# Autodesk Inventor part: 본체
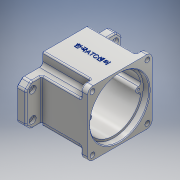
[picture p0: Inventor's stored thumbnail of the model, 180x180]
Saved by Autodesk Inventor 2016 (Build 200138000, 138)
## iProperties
Created: 2017-01
Part Number: 본체
Material: 알루미늄 6061
Document SubType Name: Modeling
Designer: Owner
Mass: 876.665 g
Surface Area: 765.409 cm^2
Volume: 324.691 cm^3
Density: 2.7 g/cm^3
Appearance: 알루미늄 - 평지
Author: Owner
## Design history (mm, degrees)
sketch "스케치1"
  geometry: L1 (-47, 47)-(47, 47); L2 (47, 47)-(47, -47); L3 (47, -47)-(-47, -47); L4 (-47, -47)-(-47, 47); L5 (-47, 47)-(47, -47); L6 (47, 47)-(-47, -47); 1 further point
  constraints: 12 end point, 2 midpoint, 2 parallel, 1 horizontal, 1 perpendicular
  dimensions: "d0" = 94 distance of L2.end L3.end; "d1" = 94 distance of L1.end L2.end
extrude "돌출1" new body sketch "스케치1" distance "d2" = 80; taper "d3" = 0 deg
sketch "스케치2"
  geometry: L1 (30, 70)-(-30, 70); L2 (-30, -70)-(30, -70); L3 (30, 70)-(-30, -70); L4 (-30, 70)-(30, -70); L5 (47, -33)-(47, 33); L6 (-47, 33)-(-47, -33); L7 (-47, -33)-(47, 33); L8 (47, -33)-(-47, 33); L9 (-47, -33)-(-30, -33); L10 (30, -33)-(47, -33); L11 (30, -70)-(30, -33); L12 (30, 33)-(30, 70); L13 (47, 33)-(30, 33); L14 (-30, 33)-(-47, 33); L15 (-30, 70)-(-30, 33); L16 (-30, -33)-(-30, -70); 9 further points
  constraints: 32 end point, 12 midpoint, 10 parallel, 4 perpendicular, 3 horizontal, 2 horizontal alignment, 2 vertical alignment
  dimensions: "d4" = 60 distance of L2.start L2.end; "d5" = 66 distance of L5.start L5.end; "d6" = 140 distance between parallel lines of L2 L1; "d7" = 94 distance between parallel lines of L6 L5
extrude "돌출2" join sketch "스케치2" distance "d8" = 13; taper "d9" = 0 deg
sketch "스케치3"
  geometry: L1 (47, -47)-(47, 47) reference; L2 (47, -47)-(30, -47); L3 (30, -47)-(30, -33); L4 (30, -33)-(47, -33); L5 (47, -33)-(47, -47); 1 further point
  constraints: 8 end point, 2 parallel, 1 horizontal, 1 perpendicular
  dimensions: "d10" = 17 distance of L3.end L4.end; "d11" = 14 distance of L2.end L3.end
extrude "돌출3" cut sketch "스케치3" distance "d12" = 70; taper "d13" = 0 deg
hole "구멍1" diameter "d32" = 80; stored, may be unused: countersink angle "d36" = 90 deg, drill point angle "d38" = 0 deg; dims "d30" = 47, "d31" = 47, "d33" = 6, "d34" = 4, "d35" = 2, "d37" = 71
hole "구멍2" diameter "d41" = 86; stored, may be unused: countersink angle "d45" = 90 deg, drill point angle "d47" = 0 deg; dims "d39" = 10, "d40" = 10, "d42" = 6, "d43" = 4, "d44" = 2, "d46" = 9
sketch "스케치8"
  geometry: A1 r 21 centre (-11, 0) between (7.984, 8.978) and (7.984, -8.978); A2 r 15 centre (20, 0) between (7.984, -8.978) and (7.984, 8.978); 1 further point
  constraints: 4 point on circle, 2 centre point, 2 horizontal alignment
  dimensions: "d48" = 42 diameter of A1; "d49" = 11 distance of point (0, 0) A1.centre; "d50" = 30 diameter of A2; "d51" = 20 distance of point (0, 0) A2.centre
extrude "돌출6" join sketch "스케치8" distance "d52" = 7; taper "d53" = 0 deg
hole "구멍3" diameter "d56" = 22; stored, may be unused: countersink angle "d60" = 90 deg, drill point angle "d62" = 0 deg; dims "d54" = 10, "d55" = 10, "d57" = 6, "d58" = 4, "d59" = 2, "d61" = 7
hole "구멍4" diameter "d65" = 19; stored, may be unused: countersink angle "d69" = 90 deg, drill point angle "d71" = 0 deg; dims "d63" = 10, "d64" = 10, "d66" = 6, "d67" = 4, "d68" = 2, "d70" = 1
hole "구멍5" diameter "d80" = 25; stored, may be unused: countersink angle "d84" = 90 deg, drill point angle "d86" = 0 deg; dims "d78" = 10, "d79" = 10, "d81" = 6, "d82" = 4, "d83" = 2, "d85" = 1
hole "구멍6" diameter "d89" = 35; stored, may be unused: countersink angle "d93" = 90 deg, drill point angle "d95" = 0 deg; dims "d87" = 10, "d88" = 10, "d90" = 6, "d91" = 4, "d92" = 2, "d94" = 10
sketch "스케치10"
  geometry: A1 r 4 centre (0, 36) between (-3.997, 35.852) and (3.997, 35.852); A2 r 40 centre (0, 0) between (8.214, 39.148) and (-8.214, 39.148) reference; A3 r 3.5 centre (-7.495, 35.722) between (-3.997, 35.852) and (-8.214, 39.148); A4 r 3.5 centre (7.495, 35.722) between (8.214, 39.148) and (3.997, 35.852); 1 further point
  constraints: 8 point on circle, 4 tangent, 3 centre point, 1 vertical alignment
  dimensions: "d105" = 8 diameter of A1; "d106" = 36 distance of A1.centre point (0, 0); "d107" = 7 diameter of A3; "d108" = 7 diameter of A4
extrude "돌출7" join sketch "스케치10" stored distance "d109" = 7; taper "d110" = 0 deg
hole "구멍8" diameter "d113" = 7; stored, may be unused: countersink angle "d117" = 90 deg, drill point angle "d119" = 0 deg; dims "d111" = 7, "d112" = 7, "d114" = 6, "d115" = 4, "d116" = 2, "d118" = 8
hole "구멍9" diameter "d122" = 4; stored, may be unused: countersink angle "d126" = 90 deg, drill point angle "d128" = 0 deg; dims "d120" = 11, "d121" = 10, "d123" = 6, "d124" = 10, "d125" = 4, "d127" = 8
hole "구멍10" diameter "d131" = 3.242; stored, may be unused: countersink angle "d135" = 90 deg, drill point angle "d137" = 118 deg; dims "d129" = 10, "d130" = 10, "d132" = 7, "d133" = 10, "d134" = 4, "d136" = 9
fillet "모깎기1" dims "d138" = 0.3
fillet "모깎기2" dims "d139" = 2
fillet "모깎기3" dims "d143" = 8
fillet "모깎기5" dims "d145" = 5
chamfer "모따기2" distance "d146" = 1; stored, may be unused: second distance "d147" = 2, angle "d148" = 45 deg
fillet "모깎기6" dims "d149" = 3
fillet "모깎기7" dims "d150" = 2
fillet "모깎기8" dims "d151" = 2
fillet "모깎기9" dims "d152" = 2
sketch "스케치11"
  geometry: L1 (0, 0)-(0, 78) reference; 3 further points
  constraints: 1 horizontal alignment, 1 midpoint, 1 other
  dimensions: "d154" = 40 distance of point (-40, 39) point (0, 39)
chamfer "모따기3" distance "d155" = 8; stored, may be unused: second distance "d156" = 2, angle "d157" = 45 deg
sketch "스케치12"
  geometry: C1 r 27.5 at (11, 0); C2 r 12.5 at (11, 0) reference; 1 further point
  constraints: 1 centre point, 1 coincident
  dimensions: "d158" = 55 diameter of C1
extrude "돌출8" join sketch "스케치12" distance "d159" = 7; taper "d160" = 0 deg
feature "엠보싱1" dims "d4" = 60, "d5" = 66, "d6" = 140, "d7" = 94, "d161" = 0.5, "d162" = 0
hole "구멍11" diameter "d165" = 32; stored, may be unused: countersink angle "d169" = 90 deg, drill point angle "d171" = 0 deg; dims "d163" = 10, "d164" = 10, "d166" = 7, "d167" = 10, "d168" = 4, "d170" = 8
fillet "모깎기11" dims "d172" = 5
fillet "모깎기12" dims "d173" = 2
sketch "스케치13"
  geometry: L1 (45, 33)-(35, 33) reference; L2 (30, 38)-(30, 59.929) reference; L3 (23.464, 68.536)-(28.536, 63.464) reference; L4 (19.929, 70)-(-19.929, 70) reference; L5 (-28.536, 63.464)-(-23.464, 68.536) reference; L6 (-30, 59.929)-(-30, 38) reference; L7 (-35, 33)-(-45, 33) reference; L8 (-47, 31)-(-47, -31) reference; L9 (-45, -33)-(-35, -33) reference; L10 (-30, -38)-(-30, -59.929) reference; L11 (-23.464, -68.536)-(-28.536, -63.464) reference; L12 (-19.929, -70)-(19.929, -70) reference; L13 (28.536, -63.464)-(23.464, -68.536) reference; L14 (30, -59.929)-(30, -38) reference; L15 (35, -33)-(45, -33) reference; L16 (47, -31)-(47, 31) reference; L17 (29, -38)-(29, -59.929); L18 (27.828, -62.757)-(22.757, -67.828); L19 (19.929, -69)-(-19.929, -69); L20 (-22.757, -67.828)-(-27.828, -62.757); L21 (-29, -59.929)-(-29, -38); L22 (-35, -32)-(-45, -32); L23 (-46, -31)-(-46, 31); L24 (-45, 32)-(-35, 32); L25 (-29, 38)-(-29, 59.929); L26 (-27.828, 62.757)-(-22.757, 67.828); L27 (-19.929, 69)-(19.929, 69); L28 (22.757, 67.828)-(27.828, 62.757); L29 (29, 59.929)-(29, 38); L30 (35, 32)-(45, 32); L31 (46, 31)-(46, -31); L32 (45, -32)-(35, -32); C1 r 27.5 at (11, 0) reference; C2 r 2 at (-19, 60) reference; C3 r 2 at (19, 60) reference; C4 r 2 at (-19, -60) reference; C5 r 2 at (19, -60) reference; A1 r 2 centre (45, 31) between (47, 31) and (45, 33) reference; A2 r 5 centre (35, 38) between (30, 38) and (35, 33) reference; A3 r 5 centre (25, 59.929) between (30, 59.929) and (28.536, 63.464) reference; A4 r 5 centre (19.929, 65) between (23.464, 68.536) and (19.929, 70) reference; A5 r 5 centre (-19.929, 65) between (-19.929, 70) and (-23.464, 68.536) reference; A6 r 5 centre (-25, 59.929) between (-28.536, 63.464) and (-30, 59.929) reference; A7 r 5 centre (-35, 38) between (-35, 33) and (-30, 38) reference; A8 r 2 centre (-45, 31) between (-45, 33) and (-47, 31) reference; A9 r 2 centre (-45, -31) between (-47, -31) and (-45, -33) reference; A10 r 5 centre (-35, -38) between (-30, -38) and (-35, -33) reference; A11 r 5 centre (-25, -59.929) between (-30, -59.929) and (-28.536, -63.464) reference; A12 r 5 centre (-19.929, -65) between (-23.464, -68.536) and (-19.929, -70) reference; A13 r 5 centre (19.929, -65) between (19.929, -70) and (23.464, -68.536) reference; A14 r 5 centre (25, -59.929) between (28.536, -63.464) and (30, -59.929) reference; A15 r 5 centre (35, -38) between (35, -33) and (30, -38) reference; A16 r 2 centre (45, -31) between (45, -33) and (47, -31) reference; A17 r 4 centre (25, -59.929) between (27.828, -62.757) and (29, -59.929); A18 r 4 centre (19.929, -65) between (19.929, -69) and (22.757, -67.828); A19 r 4 centre (-19.929, -65) between (-22.757, -67.828) and (-19.929, -69); A20 r 4 centre (-25, -59.929) between (-29, -59.929) and (-27.828, -62.757); A21 r 6 centre (-35, -38) between (-29, -38) and (-35, -32); A22 r 1 centre (-45, -31) between (-46, -31) and (-45, -32); A23 r 1 centre (-45, 31) between (-45, 32) and (-46, 31); A24 r 6 centre (-35, 38) between (-35, 32) and (-29, 38); A25 r 4 centre (-25, 59.929) between (-27.828, 62.757) and (-29, 59.929); A26 r 4 centre (-19.929, 65) between (-19.929, 69) and (-22.757, 67.828); A27 r 4 centre (19.929, 65) between (22.757, 67.828) and (19.929, 69); A28 r 4 centre (25, 59.929) between (29, 59.929) and (27.828, 62.757); A29 r 6 centre (35, 38) between (29, 38) and (35, 32); A30 r 1 centre (45, 31) between (46, 31) and (45, 32); A31 r 1 centre (45, -31) between (45, -32) and (46, -31); A32 r 6 centre (35, -38) between (35, -32) and (29, -38); 1 further point
  constraints: 32 end point, 32 point on circle, 16 centre point, 31 other
  dimensions: "d174" = 1 distance between parallel lines of L14 L17
extrude "돌출9" cut sketch "스케치13" distance "d175" = 1; taper "d176" = 0 deg
chamfer "모따기4" distance "d177" = 1; stored, may be unused: second distance "d178" = 2, angle "d179" = 45 deg
fillet "모깎기13" dims "d180" = 0.3
fillet "모깎기14" dims "d181" = 0.3
node "솔리드1"
mirror "대칭1"
mirror "대칭2"
mirror "대칭3"
mirror "대칭4"
mirror "대칭5"
mirror "대칭6"
mirror "대칭7"
mirror "대칭8"
node "투영된 루프2"
